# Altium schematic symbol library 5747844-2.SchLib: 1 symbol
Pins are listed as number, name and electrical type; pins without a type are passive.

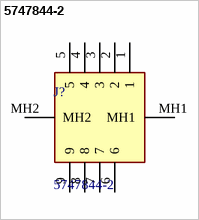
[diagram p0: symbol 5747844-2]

## 5747844-2
designator J?
09 MSFL RCPT RA 318 (FM,BL); Manufacturer_Name: TE Connectivity; Geometry.Height: 12.9286mm
footprint 57478442
pins: 1, 2, 3, 4, 5, 6, 7, 8, 9, MH1, MH2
